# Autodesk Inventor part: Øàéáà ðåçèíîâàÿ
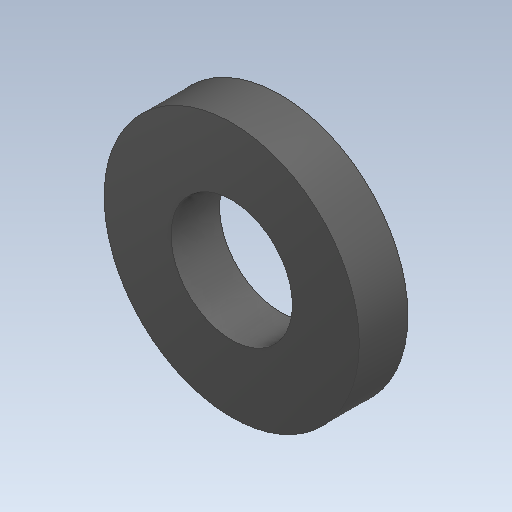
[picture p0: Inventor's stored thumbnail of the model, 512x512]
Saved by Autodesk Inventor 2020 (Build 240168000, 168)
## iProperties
Created: 1900-01
Part Number: Øàéáà ðåçèíîâàÿ
Material: Générique
Document SubType Name: Modeling
Designer: bruno
Density: 1 g/cm^3
Appearance: Par défaut
Author: bruno
Revision Number: ANYUNSPECIFIED
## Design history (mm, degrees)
feature "Base1"
node "Solide1"
